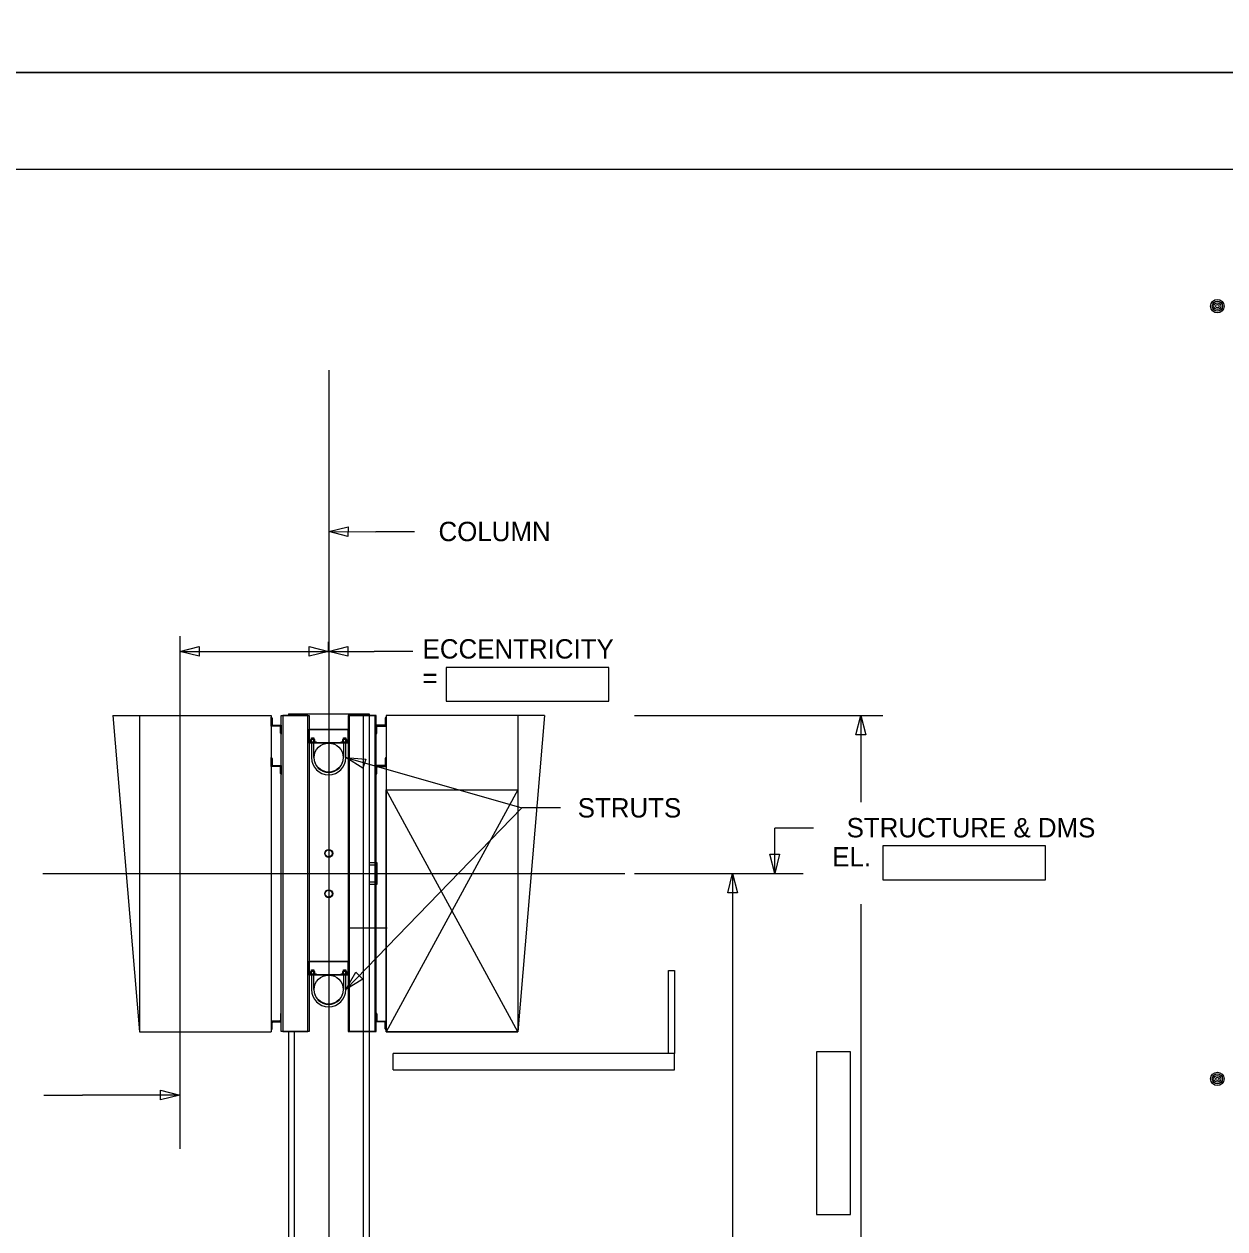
# Model space of a CAD drawing. Extents: x 3829340 to 3831660, y 499389 to 501171.
# Drawn here: x 3829781.8 to 3829967.9, y 499804 to 499990.7 of the extents above; entities that cross this region are included whole.
import ezdxf

# ---------------------------------------------------------------- set-up
doc = ezdxf.new("R2010")
doc.units = 0
for name, color, linetype in [('2', 7, 'Continuous'), ('CNTR', 7, 'Continuous'), ('DIM TXT', 7, 'Continuous'), ('PLT-BNDY', 7, 'Continuous'), ('sign', 7, 'Continuous'), ('structure', 7, 'Continuous')]:
    doc.layers.add(name, color=color, linetype=linetype)

msp = doc.modelspace()

# ---------------------------------------------------------------- linework, layer by layer
at = {"layer": '2'}
msp.add_line((3829379.96, 499968.19), (3830165.96, 499968.19), dxfattribs=at)
at = {"layer": 'CNTR'}
for p, q in [((3829829.01, 499937.06), (3829829.01, 499682.67)), ((3829805.92, 499895.86), (3829805.92, 499816.44)), ((3829784.7, 499859.09), (3829874.92, 499859.09))]:
    msp.add_line(p, q, dxfattribs=at)
at = {"layer": 'DIM TXT'}
for p, q in [((3829829.01, 499912.06), (3829836.33, 499912.03)), ((3829842.33, 499912.03), (3829836.33, 499912.03)), ((3829805.92, 499894.36), (3829805.92, 499892.01)), ((3829828.99, 499893.51), (3829828.99, 499895.01)), ((3829805.92, 499893.51), (3829828.99, 499893.51)), ((3829828.99, 499893.51), (3829836.06, 499893.51)), ((3829842.06, 499893.51), (3829836.06, 499893.51)), ((3829876.42, 499883.6), (3829914.89, 499883.6)), ((3829911.49, 499883.6), (3829911.49, 499870.15)), ((3829831.68, 499877.06), (3829858.95, 499869.28)), ((3829831.68, 499841.12), (3829858.95, 499869.28)), ((3829864.95, 499869.28), (3829858.95, 499869.28)), ((3829904.15, 499866.14), (3829898.15, 499866.14)), ((3829898.16, 499859.09), (3829898.15, 499866.14)), ((3829876.42, 499859.09), (3829902.55, 499859.09)), ((3829891.62, 499859.09), (3829891.62, 499709.1)), ((3829911.49, 499854.37), (3829911.49, 499709.1)), ((3829832.06, 499850.7), (3829838.06, 499850.7)), ((3829832.06, 499850.7), (3829838.06, 499850.7)), ((3829784.84, 499824.79), (3829790.84, 499824.79)), ((3829805.92, 499824.79), (3829790.84, 499824.79))]:
    msp.add_line(p, q, dxfattribs=at)
for points in [[(3829832, 499911.3), (3829829.01, 499912.06), (3829832.01, 499912.8)], [(3829808.92, 499892.76), (3829805.92, 499893.51), (3829808.92, 499894.26)], [(3829825.99, 499894.26), (3829828.99, 499893.51), (3829825.99, 499892.76)], [(3829831.99, 499892.76), (3829828.99, 499893.51), (3829831.99, 499894.26)], [(3829847.23, 499885.78), (3829872.42, 499885.78), (3829872.42, 499891.03), (3829847.23, 499891.03)], [(3829910.74, 499880.6), (3829911.49, 499883.6), (3829912.24, 499880.6)], [(3829834.28, 499875.4), (3829831.68, 499877.06), (3829834.76, 499876.82)], [(3829898.9, 499862.09), (3829898.16, 499859.09), (3829897.4, 499862.09)], [(3829914.89, 499858.12), (3829940.09, 499858.12), (3829940.09, 499863.37), (3829914.89, 499863.37)], [(3829890.87, 499856.09), (3829891.62, 499859.09), (3829892.37, 499856.09)], [(3829834.3, 499842.76), (3829831.68, 499841.12), (3829833.23, 499843.8)], [(3829909.87, 499806.26), (3829909.87, 499831.46), (3829904.62, 499831.46), (3829904.62, 499806.26)], [(3829802.92, 499825.54), (3829805.92, 499824.79), (3829802.92, 499824.04)]]:
    msp.add_lwpolyline(points, close=True, dxfattribs=at)
for centre, radius in [((3829966.75, 499946.99), 1.04), ((3829966.75, 499946.99), 0.783), ((3829966.75, 499946.99), 0.522), ((3829966.75, 499946.99), 0.261), ((3829966.75, 499946.99), 0.00000209), ((3829966.75, 499827.29), 1.04), ((3829966.75, 499827.29), 0.783), ((3829966.75, 499827.29), 0.522), ((3829966.75, 499827.29), 0.261), ((3829966.75, 499827.29), 0.00000209)]:
    msp.add_circle(centre, radius, dxfattribs=at)
at = {"layer": 'PLT-BNDY'}
for points in [[(3829339.96, 500577.19), (3830180.96, 500577.19), (3830180.96, 499983.19), (3829339.96, 499983.19)], [(3829339.96, 499983.19), (3830180.96, 499983.19), (3830180.96, 499389.19), (3829339.96, 499389.19)]]:
    msp.add_lwpolyline(points, close=True, dxfattribs=at)
at = {"layer": 'sign'}
for p, q in [((3829795.57, 499883.6), (3829799.67, 499834.58)), ((3829795.57, 499883.6), (3829820.11, 499883.6)), ((3829799.67, 499883.6), (3829799.67, 499834.58)), ((3829820.11, 499883.6), (3829820.11, 499834.58)), ((3829820.11, 499881.93), (3829820.11, 499883.3)), ((3829820.24, 499883.17), (3829820.24, 499882.19)), ((3829837.78, 499883.17), (3829837.78, 499882.19)), ((3829837.91, 499883.6), (3829837.91, 499834.58)), ((3829862.45, 499883.6), (3829837.91, 499883.6)), ((3829837.91, 499881.93), (3829837.91, 499883.3)), ((3829858.34, 499883.6), (3829858.34, 499834.58)), ((3829862.45, 499883.6), (3829858.34, 499834.58)), ((3829821.41, 499881.93), (3829820.11, 499881.93)), ((3829820.37, 499882.06), (3829821.67, 499882.06)), ((3829821.54, 499880.82), (3829821.54, 499881.8)), ((3829821.67, 499882.06), (3829821.67, 499880.69)), ((3829837.65, 499882.06), (3829836.35, 499882.06)), ((3829836.35, 499882.06), (3829836.35, 499880.69)), ((3829836.48, 499880.82), (3829836.48, 499881.8)), ((3829836.61, 499881.93), (3829837.91, 499881.93)), ((3829826.73, 499879.31), (3829826.34, 499879.31)), ((3829826.34, 499879.31), (3829826.34, 499877.06)), ((3829826.37, 499879.49), (3829826.37, 499879.8)), ((3829826.7, 499879.49), (3829826.7, 499879.8)), ((3829826.73, 499877.06), (3829826.73, 499879.31)), ((3829831.68, 499879.31), (3829831.29, 499879.31)), ((3829831.29, 499879.31), (3829831.29, 499877.06)), ((3829831.32, 499879.49), (3829831.32, 499879.8)), ((3829831.65, 499879.49), (3829831.65, 499879.8)), ((3829831.65, 499879.49), (3829831.65, 499879.8)), ((3829831.68, 499877.06), (3829831.68, 499879.31)), ((3829820.11, 499875.68), (3829820.11, 499877.05)), ((3829837.91, 499875.68), (3829837.91, 499877.05)), ((3829821.41, 499875.68), (3829820.11, 499875.68)), ((3829820.24, 499876.92), (3829820.24, 499875.94)), ((3829820.37, 499875.81), (3829821.67, 499875.81)), ((3829821.54, 499874.58), (3829821.54, 499875.55)), ((3829821.67, 499875.81), (3829821.67, 499874.44)), ((3829837.65, 499875.81), (3829836.35, 499875.81)), ((3829836.35, 499875.81), (3829836.35, 499874.44)), ((3829836.48, 499874.58), (3829836.48, 499875.55)), ((3829836.61, 499875.68), (3829837.91, 499875.68)), ((3829837.78, 499876.92), (3829837.78, 499875.94)), ((3829826.37, 499843.55), (3829826.37, 499843.87)), ((3829826.7, 499843.55), (3829826.7, 499843.87)), ((3829831.32, 499843.55), (3829831.32, 499843.87)), ((3829831.65, 499843.55), (3829831.65, 499843.87)), ((3829831.65, 499843.55), (3829831.65, 499843.87)), ((3829826.73, 499843.37), (3829826.34, 499843.37)), ((3829826.34, 499843.37), (3829826.34, 499841.12)), ((3829826.73, 499841.12), (3829826.73, 499843.37)), ((3829831.68, 499843.37), (3829831.29, 499843.37)), ((3829831.29, 499843.37), (3829831.29, 499841.12)), ((3829831.68, 499841.12), (3829831.68, 499843.37)), ((3829820.11, 499836.25), (3829820.11, 499834.89)), ((3829821.41, 499836.25), (3829820.11, 499836.25)), ((3829820.24, 499835.02), (3829820.24, 499835.99)), ((3829820.37, 499836.12), (3829821.67, 499836.12)), ((3829821.54, 499837.36), (3829821.54, 499836.38)), ((3829821.67, 499836.12), (3829821.67, 499837.49)), ((3829836.35, 499836.12), (3829836.35, 499837.49)), ((3829837.65, 499836.12), (3829836.35, 499836.12)), ((3829836.48, 499837.36), (3829836.48, 499836.38)), ((3829836.61, 499836.25), (3829837.91, 499836.25)), ((3829837.78, 499835.02), (3829837.78, 499835.99)), ((3829837.91, 499836.25), (3829837.91, 499834.89)), ((3829799.67, 499834.58), (3829820.11, 499834.58)), ((3829858.34, 499834.58), (3829837.91, 499834.58)), ((3829839.01, 499828.7), (3829839.01, 499831.2))]:
    msp.add_line(p, q, dxfattribs=at)
for points in [[(3829825.98, 499883.57), (3829825.98, 499834.61), (3829821.67, 499834.61), (3829821.67, 499883.57)], [(3829825.77, 499834.61), (3829825.77, 499883.57), (3829821.88, 499883.57), (3829821.88, 499834.61)], [(3829832.03, 499883.57), (3829832.03, 499834.61), (3829836.35, 499834.61), (3829836.35, 499883.57)], [(3829832.24, 499834.61), (3829832.24, 499883.57), (3829836.14, 499883.57), (3829836.14, 499834.61)], [(3829825.98, 499881.46), (3829832.03, 499881.46), (3829832.03, 499879.31), (3829825.98, 499879.31)], [(3829832.03, 499881.36), (3829825.98, 499881.36), (3829825.98, 499879.41), (3829832.03, 499879.41)], [(3829827.08, 499879.41), (3829825.99, 499879.41), (3829825.99, 499879.49), (3829827.08, 499879.49)], [(3829832.03, 499879.41), (3829830.93, 499879.41), (3829830.93, 499879.49), (3829832.03, 499879.49)], [(3829858.34, 499834.58), (3829837.91, 499834.58), (3829837.91, 499872.08), (3829858.34, 499872.08)], [(3829825.98, 499845.53), (3829832.03, 499845.53), (3829832.03, 499843.37), (3829825.98, 499843.37)], [(3829832.03, 499845.42), (3829825.98, 499845.42), (3829825.98, 499843.47), (3829832.03, 499843.47)], [(3829827.08, 499843.47), (3829825.99, 499843.47), (3829825.99, 499843.55), (3829827.08, 499843.55)], [(3829832.03, 499843.47), (3829830.93, 499843.47), (3829830.93, 499843.55), (3829832.03, 499843.55)], [(3829882.63, 499831.2), (3829881.69, 499831.2), (3829881.69, 499844.08), (3829882.63, 499844.08)]]:
    msp.add_lwpolyline(points, close=True, dxfattribs=at)
for points in [[(3829826.2, 499879.8), (3829826.2, 499879.49), (3829826.87, 499879.49), (3829826.87, 499879.8)], [(3829826.83, 499879.84), (3829826.24, 499879.84)], [(3829826.34, 499879.84), (3829826.34, 499880.11), (3829826.73, 499880.11), (3829826.73, 499879.84)], [(3829831.15, 499879.8), (3829831.15, 499879.49), (3829831.81, 499879.49), (3829831.81, 499879.8)], [(3829831.78, 499879.84), (3829831.19, 499879.84)], [(3829831.29, 499879.84), (3829831.29, 499880.11), (3829831.68, 499880.11), (3829831.68, 499879.84)], [(3829858.34, 499872.08), (3829837.91, 499834.58), (3829858.34, 499834.58), (3829837.91, 499872.08)], [(3829826.2, 499843.87), (3829826.2, 499843.55), (3829826.87, 499843.55), (3829826.87, 499843.87)], [(3829826.83, 499843.9), (3829826.24, 499843.9)], [(3829826.34, 499843.9), (3829826.34, 499844.17), (3829826.73, 499844.17), (3829826.73, 499843.9)], [(3829831.15, 499843.87), (3829831.15, 499843.55), (3829831.81, 499843.55), (3829831.81, 499843.87)], [(3829831.78, 499843.9), (3829831.19, 499843.9)], [(3829831.29, 499843.9), (3829831.29, 499844.17), (3829831.68, 499844.17), (3829831.68, 499843.9)], [(3829839.01, 499828.7), (3829882.63, 499828.7), (3829882.63, 499831.2), (3829839.01, 499831.2)]]:
    msp.add_lwpolyline(points, dxfattribs=at)
for centre, radius, start, end in [((3829820.11, 499883.17), 0.13, 0, 90), ((3829837.91, 499883.17), 0.13, 90, 180), ((3829820.37, 499882.19), 0.13, 180, 270), ((3829821.41, 499881.8), 0.13, 0, 90), ((3829821.67, 499880.82), 0.13, 180, 270), ((3829836.35, 499880.82), 0.13, 270, 360), ((3829836.61, 499881.8), 0.13, 90, 180), ((3829837.65, 499882.19), 0.13, 270, 360), ((3829826.24, 499879.8), 0.0375, 90, 180), ((3829826.33, 499879.8), 0.0375, 0, 90), ((3829826.74, 499879.8), 0.0375, 90, 180), ((3829826.83, 499879.8), 0.0375, 0, 90), ((3829831.19, 499879.8), 0.0375, 90, 180), ((3829831.28, 499879.8), 0.0375, 0, 90), ((3829831.68, 499879.8), 0.0375, 90, 180), ((3829831.68, 499879.8), 0.0375, 90, 180), ((3829831.78, 499879.8), 0.0375, 0, 90), ((3829831.78, 499879.8), 0.0375, 0, 90), ((3829820.11, 499876.92), 0.13, 0, 90), ((3829829.01, 499877.06), 2.67, 180, 0), ((3829829.01, 499877.06), 2.28, 180, 0), ((3829837.91, 499876.92), 0.13, 90, 180), ((3829820.37, 499875.94), 0.13, 180, 270), ((3829821.41, 499875.55), 0.13, 0, 90), ((3829836.61, 499875.55), 0.13, 90, 180), ((3829837.65, 499875.94), 0.13, 270, 360), ((3829821.67, 499874.58), 0.13, 180, 270), ((3829836.35, 499874.58), 0.13, 270, 360), ((3829826.24, 499843.87), 0.0375, 90, 180), ((3829826.33, 499843.87), 0.0375, 0, 90), ((3829826.74, 499843.87), 0.0375, 90, 180), ((3829826.83, 499843.87), 0.0375, 0, 90), ((3829831.19, 499843.87), 0.0375, 90, 180), ((3829831.28, 499843.87), 0.0375, 0, 90), ((3829831.68, 499843.87), 0.0375, 90, 180), ((3829831.68, 499843.87), 0.0375, 90, 180), ((3829831.78, 499843.87), 0.0375, 0, 90), ((3829831.78, 499843.87), 0.0375, 0, 90), ((3829829.01, 499841.12), 2.67, 180, 0), ((3829829.01, 499841.12), 2.28, 180, 0), ((3829820.37, 499835.99), 0.13, 90, 180), ((3829821.41, 499836.38), 0.13, 270, 360), ((3829821.67, 499837.36), 0.13, 90, 180), ((3829836.35, 499837.36), 0.13, 0, 90), ((3829836.61, 499836.38), 0.13, 180, 270), ((3829837.65, 499835.99), 0.13, 0, 90), ((3829820.11, 499835.02), 0.13, 270, 0), ((3829837.91, 499835.02), 0.13, 180, 270)]:
    msp.add_arc(centre, radius, start, end, dxfattribs=at)
for centre, major_axis, start_param, end_param in [((3829826.47, 499879.8), (-0.104, 0), 4.712389, 6.283185), ((3829826.6, 499879.8), (0.104, 0), 0, 1.570796), ((3829831.42, 499879.8), (-0.104, 0), 4.712389, 6.283185), ((3829831.54, 499879.8), (0.104, 0), 0, 1.570796), ((3829826.47, 499843.87), (-0.104, 0), 4.712389, 6.283185), ((3829826.6, 499843.87), (0.104, 0), 0, 1.570796), ((3829831.42, 499843.87), (-0.104, 0), 4.712389, 6.283185), ((3829831.54, 499843.87), (0.104, 0), 0, 1.570796)]:
    msp.add_ellipse(centre, major_axis=major_axis, ratio=0.362172, start_param=start_param, end_param=end_param, dxfattribs=at)
at = {"layer": 'structure'}
for p, q in [((3829822.76, 499883.83), (3829835.26, 499883.83)), ((3829822.76, 499883.83), (3829822.76, 499883.57)), ((3829823.02, 499883.83), (3829823.02, 499883.57)), ((3829834.36, 499883.83), (3829834.36, 499755.23)), ((3829835, 499883.83), (3829835, 499883.57)), ((3829835.26, 499883.83), (3829835.26, 499755.23)), ((3829835.26, 499883.83), (3829835.26, 499883.57)), ((3829822.76, 499834.61), (3829822.76, 499755.23)), ((3829822.76, 499834.61), (3829822.76, 499755.23)), ((3829823.66, 499834.61), (3829823.66, 499755.23))]:
    msp.add_line(p, q, dxfattribs=at)
for points in [[(3829835.26, 499860.79), (3829836.49, 499860.79), (3829836.49, 499857.4), (3829835.26, 499857.4)], [(3829835.26, 499860.79), (3829836.49, 499860.79), (3829836.49, 499857.4), (3829835.26, 499857.4)], [(3829835.26, 499857.79), (3829836.49, 499857.79), (3829836.49, 499860.39), (3829835.26, 499860.39)], [(3829835.26, 499857.79), (3829836.49, 499857.79), (3829836.49, 499860.39), (3829835.26, 499860.39)]]:
    msp.add_lwpolyline(points, dxfattribs=at)
for centre, radius in [((3829829.01, 499877.06), 2.25), ((3829829.01, 499862.22), 0.618), ((3829829.01, 499862.22), 0.538), ((3829829.01, 499855.97), 0.618), ((3829829.01, 499855.97), 0.538), ((3829829.01, 499841.12), 2.25)]:
    msp.add_circle(centre, radius, dxfattribs=at)

# ---------------------------------------------------------------- texts
at = {"layer": 'DIM TXT'}
for s, height, p in [('  COLUMN', 3, (3829843.8, 499910.59)), ('ECCENTRICITY', 2.9999, (3829843.56, 499892.4)), ('=', 3, (3829843.56, 499887.9)), ('STRUTS', 3, (3829867.61, 499867.78)), ('  STRUCTURE & DMS', 2.9999, (3829907.06, 499864.7)), ('EL.', 3, (3829907.06, 499860.2))]:
    msp.add_text(s, height=height, dxfattribs=at).set_placement(p)

doc.saveas('drawing.dxf')
